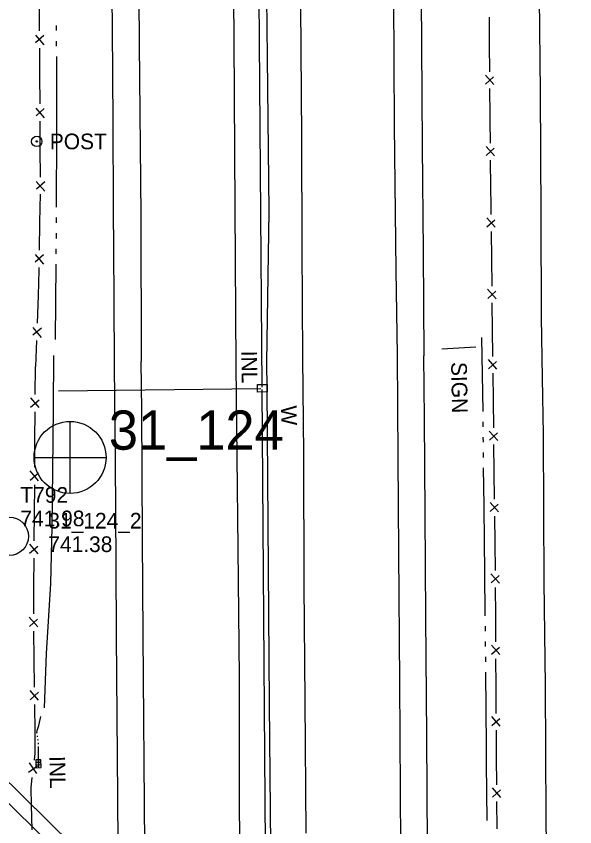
# Model space of a CAD drawing. Extents: x 589250 to 1188077, y 162953 to 363065.
# Drawn here: x 594152 to 594365.9, y 168901.4 to 169211.6 of the extents above; entities that cross this region are included whole.
import ezdxf

# ---------------------------------------------------------------- set-up
doc = ezdxf.new("R2010")
doc.units = 0
for name, color, linetype in [('E_DRN', 7, 'Continuous'), ('E_DRN_Pipe', 7, 'Continuous'), ('E_DRN_SS_UG', 7, 'Continuous'), ('E_DRN_Text', 7, 'Continuous'), ('E_FEN_P', 7, 'Continuous'), ('E_MAP_Control', 7, 'Continuous'), ('E_MAP_PassPoints', 7, 'Continuous'), ('E_MAP_PhotoCenter', 7, 'Continuous'), ('E_MISCPROP', 7, 'Continuous'), ('E_RDWY', 7, 'Continuous'), ('E_RDWY_Gravel', 7, 'Continuous'), ('E_SGN', 7, 'Continuous'), ('E_SGN_Text', 7, 'Continuous'), ('E_WAL', 7, 'Continuous'), ('E_WAL_Text', 7, 'Continuous'), ('E_WTR_FlowLine', 7, 'Continuous')]:
    doc.layers.add(name, color=color, linetype=linetype)

msp = doc.modelspace()

# ---------------------------------------------------------------- linework, layer by layer
at = {"layer": 'E_DRN'}
for p, q in [((594244.38, 169070.63), (594248.06, 169070.65)), ((594244.4, 169067.8), (594244.38, 169070.63)), ((594248.08, 169067.82), (594244.4, 169067.8)), ((594248.06, 169070.65), (594248.08, 169067.82)), ((594161.51, 168927.09), (594159.51, 168927.05)), ((594159.51, 168927.05), (594159.57, 168924.05)), ((594161.53, 168926.09), (594159.53, 168926.05)), ((594161.55, 168925.09), (594159.55, 168925.05)), ((594160.51, 168927.07), (594160.57, 168924.07)), ((594161.57, 168924.09), (594161.51, 168927.09)), ((594159.57, 168924.05), (594161.57, 168924.09))]:
    msp.add_line(p, q, dxfattribs=at)
at = {"layer": 'E_DRN_Pipe'}
for p, q in [((594248.1, 168818.27), (594246.15, 169068.78)), ((594107.08, 168959.95), (594410.74, 168660.65)), ((594107.28, 168951.63), (594410.94, 168652.33))]:
    msp.add_line(p, q, dxfattribs=at)
at = {"layer": 'E_DRN_SS_UG'}
msp.add_line((594246.14, 169069.73), (594243.8, 169369.71), dxfattribs=at)
msp.add_lwpolyline([(594245.72, 169069.02), (594168.28, 169068.1)], dxfattribs=at)
at = {"layer": 'E_FEN_P'}
for p, q in [((594160.86, 169216.76), (594160.86, 169209.9)), ((594333.25, 169200.8), (594333.17, 169211.24)), ((594160.86, 169209.9), (594160.88, 169206.07)), ((594159.39, 169204.42), (594162.65, 169200.71)), ((594162.63, 169204.27), (594159.47, 169201.45)), ((594160.91, 169199.46), (594160.97, 169188.77)), ((594333.34, 169190.37), (594333.25, 169200.8)), ((594160.97, 169188.77), (594161.02, 169178.24)), ((594334.84, 169185.52), (594331.65, 169189.13)), ((594331.67, 169185.66), (594334.75, 169188.43)), ((594333.48, 169173.47), (594333.39, 169183.91)), ((594159.54, 169176.43), (594162.8, 169172.72)), ((594162.78, 169176.28), (594159.62, 169173.46)), ((594161.02, 169178.24), (594161.02, 169178.08)), ((594333.49, 169171.61), (594333.48, 169173.47)), ((594161.06, 169171.46), (594161.12, 169160.78)), ((594333.57, 169163.03), (594333.49, 169171.61)), ((594161.12, 169160.78), (594161.17, 169150.09)), ((594335.08, 169158.19), (594331.88, 169161.8)), ((594331.91, 169158.33), (594334.99, 169161.09)), ((594333.73, 169146.14), (594333.63, 169156.57)), ((594159.69, 169148.44), (594162.95, 169144.73)), ((594162.93, 169148.28), (594159.77, 169145.47)), ((594333.79, 169139.2), (594333.73, 169146.14)), ((594161.15, 169143.47), (594160.99, 169132.79)), ((594333.83, 169135.7), (594333.79, 169139.2)), ((594335.36, 169130.86), (594332.15, 169134.46)), ((594332.19, 169130.99), (594335.26, 169133.76)), ((594160.99, 169132.79), (594160.82, 169122.1)), ((594334.05, 169118.8), (594333.92, 169129.24)), ((594159.3, 169120.48), (594162.49, 169116.71)), ((594162.54, 169120.26), (594159.32, 169117.51)), ((594334.19, 169108.37), (594334.05, 169118.8)), ((594160.71, 169114.43), (594160.38, 169104.8)), ((594160.72, 169115.48), (594160.71, 169114.43)), ((594335.71, 169103.53), (594332.5, 169107.13)), ((594332.54, 169103.66), (594335.61, 169106.43)), ((594160.38, 169104.8), (594160.01, 169094.12)), ((594334.4, 169091.47), (594334.27, 169101.91)), ((594158.45, 169092.53), (594161.57, 169088.7)), ((594161.69, 169092.25), (594158.42, 169089.56)), ((594334.52, 169081.45), (594334.4, 169091.88)), ((594159.78, 169087.51), (594159.41, 169077.55)), ((594336.04, 169076.61), (594332.83, 169080.21)), ((594159.34, 169066.86), (594159.41, 169077.55)), ((594332.87, 169076.74), (594335.94, 169079.51)), ((594334.71, 169064.56), (594334.59, 169074.99)), ((594157.56, 169062.07), (594160.76, 169064.85)), ((594160.8, 169061.88), (594157.59, 169065.63)), ((594334.83, 169054.12), (594334.71, 169064.56)), ((594159.22, 169049.56), (594159.29, 169060.25)), ((594336.35, 169049.29), (594333.14, 169052.89)), ((594333.18, 169049.42), (594336.25, 169052.19)), ((594159.14, 169038.87), (594159.22, 169049.56)), ((594335.03, 169037.23), (594334.91, 169047.67)), ((594157.37, 169034.08), (594160.56, 169036.86)), ((594160.61, 169033.88), (594157.39, 169037.63)), ((594335.15, 169026.8), (594335.03, 169037.23)), ((594159.02, 169021.56), (594159.1, 169032.25)), ((594336.66, 169021.97), (594333.46, 169025.56)), ((594333.5, 169022.1), (594336.56, 169024.87)), ((594158.95, 169010.87), (594159.02, 169021.56)), ((594335.34, 169009.91), (594335.22, 169020.34)), ((594157.17, 169006.08), (594160.36, 169008.86)), ((594160.41, 169005.89), (594157.19, 169009.63)), ((594335.46, 168999.48), (594335.34, 169009.91)), ((594158.83, 168993.56), (594158.9, 169004.25)), ((594336.98, 168994.64), (594333.77, 168998.24)), ((594333.81, 168994.77), (594336.88, 168997.54)), ((594158.75, 168982.87), (594158.83, 168993.56)), ((594335.59, 168982.59), (594335.53, 168993.02)), ((594160.3, 168977.92), (594157.02, 168981.61)), ((594157.06, 168978.05), (594160.2, 168980.89)), ((594335.65, 168972.16), (594335.59, 168982.59)), ((594158.94, 168965.57), (594158.82, 168976.26)), ((594337.14, 168967.31), (594333.96, 168970.93)), ((594333.98, 168967.46), (594337.06, 168970.21)), ((594159.05, 168954.88), (594158.94, 168965.57)), ((594335.75, 168955.27), (594335.69, 168965.7)), ((594160.61, 168949.92), (594157.32, 168953.61)), ((594335.82, 168944.83), (594335.75, 168955.27)), ((594157.36, 168950.06), (594160.51, 168952.89)), ((594159.24, 168937.57), (594159.13, 168948.26)), ((594337.31, 168939.99), (594334.12, 168943.6)), ((594334.14, 168940.14), (594337.22, 168942.89)), ((594159.33, 168929.57), (594159.24, 168937.57)), ((594335.91, 168929.2), (594335.85, 168938.38)), ((594159, 168926.9), (594159.33, 168929.57)), ((594335.92, 168927.94), (594335.91, 168929.2)), ((594159.89, 168921.78), (594157.12, 168925.87)), ((594336.01, 168917.51), (594335.92, 168927.94)), ((594156.69, 168922.35), (594160.18, 168924.74)), ((594157.71, 168916.3), (594158.2, 168920.33)), ((594157.88, 168909.68), (594157.71, 168916.3)), ((594337.51, 168912.67), (594334.31, 168916.28)), ((594334.34, 168912.81), (594337.42, 168915.57)), ((594158.13, 168900.28), (594157.88, 168909.68)), ((594336.15, 168900.62), (594336.06, 168911.05))]:
    msp.add_line(p, q, dxfattribs=at)
at = {"layer": 'E_MAP_PassPoints'}
msp.add_circle((594149.32, 169012.59), 7.38, dxfattribs=at)
msp.add_circle((594149.32, 169012.59), 7.38, dxfattribs=at)
at = {"layer": 'E_MAP_PhotoCenter'}
for p, q in [((594172.6, 169056.57), (594172.53, 169029.16)), ((594172.6, 169056.57), (594172.53, 169029.16)), ((594158.91, 169042.76), (594186.37, 169042.75)), ((594158.91, 169042.76), (594186.37, 169042.75))]:
    msp.add_line(p, q, dxfattribs=at)
msp.add_circle((594172.65, 169042.77), 13.78, dxfattribs=at)
msp.add_circle((594172.65, 169042.77), 13.78, dxfattribs=at)
at = {"layer": 'E_MISCPROP'}
for radius in [2, 0.25]:
    msp.add_circle((594159.89, 169163.71), radius, dxfattribs=at)
at = {"layer": 'E_RDWY'}
for p, q in [((594198.47, 169266.17), (594199.11, 169201.1)), ((594234.79, 169263.33), (594235.34, 169202.58)), ((594296.39, 169226.02), (594296.77, 169169.84)), ((594352.72, 169182.59), (594352.23, 169224.57)), ((594261.39, 169165.18), (594260.93, 169215.84)), ((594199.11, 169201.1), (594199.76, 169135.55)), ((594235.34, 169202.58), (594235.72, 169138.46)), ((594352.94, 169135.42), (594352.72, 169182.59)), ((594296.77, 169169.84), (594297.35, 169114.26)), ((594261.48, 169123.19), (594261.39, 169165.18)), ((594235.72, 169138.46), (594236.07, 169077.79)), ((594199.76, 169135.55), (594199.85, 169079.45)), ((594353.14, 169096.52), (594352.94, 169135.42)), ((594261.69, 169080.93), (594261.48, 169123.19)), ((594297.35, 169114.26), (594297.92, 169082.06)), ((594353.5, 169073.18), (594353.14, 169096.52)), ((594262.09, 169044.22), (594261.69, 169080.93)), ((594297.92, 169082.06), (594298.11, 169042.81)), ((594200.12, 169060.9), (594199.85, 169079.45)), ((594236.07, 169077.79), (594236.81, 169007.95)), ((594353.83, 169051.5), (594353.5, 169073.18)), ((594200.42, 169011.81), (594200.12, 169060.9)), ((594354.02, 169022.5), (594353.83, 169051.5)), ((594262.28, 168993.93), (594262.09, 169044.22)), ((594298.11, 169042.81), (594298.38, 169006.37)), ((594354.19, 168995.23), (594354.02, 169022.5)), ((594200.63, 168974.76), (594200.42, 169011.81)), ((594236.81, 169007.95), (594237.32, 168958.54)), ((594298.38, 169006.37), (594298.75, 168956.95)), ((594262.69, 168949.77), (594262.28, 168993.93)), ((594354.65, 168955.53), (594354.19, 168995.23)), ((594201.42, 168870.07), (594200.63, 168974.76)), ((594237.32, 168958.54), (594237.35, 168913.17)), ((594298.75, 168956.95), (594299.47, 168848.47)), ((594354.84, 168904.98), (594354.65, 168955.53)), ((594263.09, 168898.96), (594262.69, 168949.77)), ((594237.35, 168913.17), (594237.71, 168864.55)), ((594355.34, 168866.73), (594354.84, 168904.98))]:
    msp.add_line(p, q, dxfattribs=at)
at = {"layer": 'E_RDWY_Gravel'}
for p, q in [((594188.44, 169243.81), (594188.72, 169207.14)), ((594306.92, 169236.17), (594307.17, 169200.58)), ((594188.72, 169207.14), (594188.99, 169170.82)), ((594307.17, 169200.58), (594307.48, 169161.84)), ((594188.99, 169170.82), (594189.18, 169138.65)), ((594307.48, 169161.84), (594307.83, 169121.63)), ((594189.18, 169138.65), (594189.41, 169103.92)), ((594307.83, 169121.63), (594308.03, 169081.66)), ((594189.41, 169103.92), (594189.56, 169077.5)), ((594308.27, 169057.72), (594308.03, 169081.66)), ((594189.56, 169077.5), (594189.89, 169041.65)), ((594308.54, 169021.21), (594308.27, 169057.72)), ((594189.89, 169041.65), (594190.21, 169002.01)), ((594308.86, 168981.63), (594308.54, 169021.21)), ((594190.21, 169002.01), (594190.31, 168974.61)), ((594309.16, 168936.07), (594308.86, 168981.63)), ((594190.31, 168974.61), (594190.84, 168912.89)), ((594309.5, 168888.25), (594309.16, 168936.07)), ((594190.84, 168912.89), (594191.05, 168879.9))]:
    msp.add_line(p, q, dxfattribs=at)
at = {"layer": 'E_SGN'}
msp.add_line((594328, 169085.04), (594314.91, 169084.27), dxfattribs=at)
at = {"layer": 'E_WAL'}
for p, q in [((594248.27, 169195.85), (594247.71, 169243.5)), ((594248.84, 169137.04), (594248.27, 169195.85)), ((594248.01, 169079.3), (594248.84, 169137.04)), ((594248.07, 169069.13), (594248.01, 169079.3)), ((594249, 168948.67), (594248.07, 169069.13)), ((594249.48, 168890.14), (594249, 168948.67))]:
    msp.add_line(p, q, dxfattribs=at)
at = {"layer": 'E_WTR_FlowLine'}
for p, q in [((594167.5, 169206.11), (594167.49, 169208.09)), ((594167.51, 169200.15), (594167.51, 169202.13)), ((594167.59, 169175.68), (594167.53, 169196.17)), ((594167.57, 169167.36), (594167.59, 169175.68)), ((594167.49, 169138.54), (594167.57, 169167.36)), ((594167.48, 169132.58), (594167.48, 169134.57)), ((594167.43, 169126.62), (594167.45, 169128.61)), ((594167.37, 169120.66), (594167.39, 169122.65)), ((594167.04, 169087.87), (594167.33, 169116.68)), ((594330.72, 169060.33), (594330.26, 169088.68)), ((594330.8, 169054.46), (594330.79, 169056.41)), ((594330.86, 169048.59), (594330.84, 169050.55)), ((594330.92, 169042.73), (594330.9, 169044.68)), ((594331.11, 169024.23), (594330.96, 169038.82)), ((594331.25, 169010.46), (594331.11, 169024.23)), ((594331.37, 168999.09), (594331.25, 169010.46)), ((594331.58, 168982.11), (594331.37, 168999.09)), ((594331.65, 168976.24), (594331.63, 168978.2)), ((594331.72, 168970.37), (594331.7, 168972.33)), ((594331.78, 168966.04), (594331.77, 168966.46)), ((594331.79, 168964.51), (594331.78, 168966.04)), ((594332.01, 168932.24), (594331.82, 168960.6)), ((594160.64, 168940.24), (594161.45, 168943.58)), ((594159.96, 168937.5), (594160.08, 168938.3)), ((594160.01, 168937.14), (594159.96, 168937.5)), ((594160.08, 168938.3), (594160.64, 168940.24)), ((594160.2, 168935.79), (594160.13, 168936.24)), ((594160.38, 168934.43), (594160.32, 168934.88)), ((594160.57, 168933.07), (594160.51, 168933.53)), ((594160.54, 168931.45), (594160.55, 168932.16)), ((594160.56, 168930.19), (594160.54, 168931.45)), ((594332.05, 168925.6), (594332.01, 168932.24)), ((594160.51, 168929.46), (594160.56, 168930.19)), ((594160.54, 168927.73), (594160.51, 168929.46)), ((594160.58, 168925.67), (594160.54, 168927.73)), ((594332.25, 168903.88), (594332.05, 168925.6))]:
    msp.add_line(p, q, dxfattribs=at)
for points in [[(594166.25, 169081.83), (594166.16, 169061.57)], [(594166.16, 169061.57), (594165.98, 169037.94)], [(594165.98, 169037.94), (594165.72, 169016.22)], [(594165.72, 169016.22), (594165.22, 168994.5)], [(594165.22, 168994.5), (594163.56, 168967.77)], [(594163.56, 168967.77), (594162.77, 168946.91)]]:
    msp.add_lwpolyline(points, dxfattribs=at)

# ---------------------------------------------------------------- texts
at = {"layer": 'E_DRN_Text'}
for rotation, p in [(271.0474, (594238.18, 169083.57)), (271.04, (594164.74, 168928.46))]:
    msp.add_text('INL', height=6, rotation=rotation, dxfattribs=at).set_placement(p)
at = {"layer": 'E_MAP_Control'}
for s, p in [('T792', (594153.62, 169025.44)), ('T792', (594153.62, 169025.44)), ('741.98', (594153.62, 169016.44)), ('741.98', (594153.62, 169016.44))]:
    msp.add_text(s, height=6, dxfattribs=at).set_placement(p)
at = {"layer": 'E_MAP_PassPoints'}
for s, p in [('31_124_2', (594164.32, 169015.57)), ('31_124_2', (594164.32, 169015.57)), ('741.38', (594164.32, 169006.57)), ('741.38', (594164.32, 169006.57))]:
    msp.add_text(s, height=6, dxfattribs=at).set_placement(p)
at = {"layer": 'E_MAP_PhotoCenter'}
msp.add_text('31_124', height=15, dxfattribs=at).set_placement((594187.5, 169045.74))
msp.add_text('31_124', height=15, dxfattribs=at).set_placement((594187.5, 169045.74))
at = {"layer": 'E_MISCPROP'}
msp.add_text('POST', height=6, dxfattribs=at).set_placement((594164.89, 169160.71))
at = {"layer": 'E_SGN_Text'}
msp.add_text('SIGN', height=6, rotation=271.0474, dxfattribs=at).set_placement((594318.52, 169079.26))
at = {"layer": 'E_WAL_Text'}
msp.add_text('W', height=6, rotation=271.0474, dxfattribs=at).set_placement((594253.37, 169062.6))

doc.saveas('drawing.dxf')
